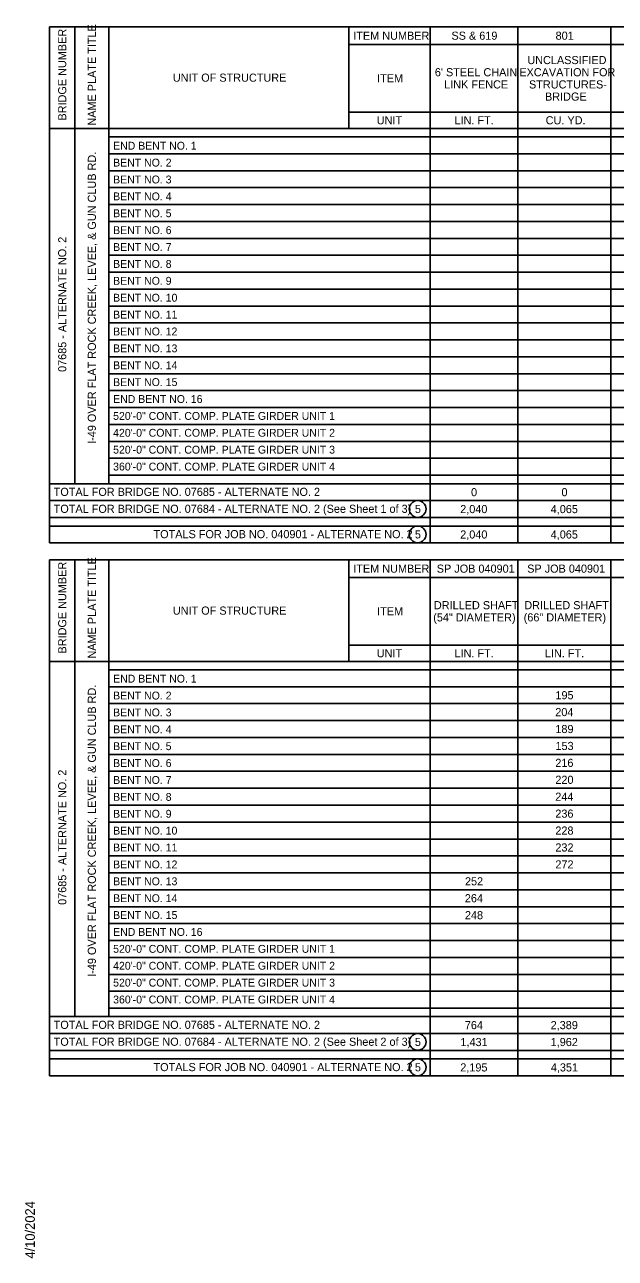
# Model space of a CAD drawing. Extents: x 0.06 to 1.36, y 0.04 to 0.85.
# Drawn here: x 0.06 to 0.423, y 0.079 to 0.838 of the extents above; entities that cross this region are included whole.
import ezdxf

# ---------------------------------------------------------------- set-up
doc = ezdxf.new("R2010")
doc.units = 0
for name, color, linetype in [('R_Shade By Others', 7, 'Continuous'), ('R_Survey Control', 7, 'Continuous'), ('R_Wall', 7, 'Continuous')]:
    doc.layers.add(name, color=color, linetype=linetype)

msp = doc.modelspace()

# ---------------------------------------------------------------- linework, layer by layer
at = {"layer": 'R_Survey Control'}
for p, q in [((0.07508, 0.51924), (0.07508, 0.83695)), ((0.07508, 0.83695), (1.33392, 0.83695)), ((0.09071, 0.5557), (0.09071, 0.83695)), ((0.11154, 0.5557), (0.11154, 0.83695)), ((0.11154, 0.77445), (0.11154, 0.83695)), ((0.2593, 0.77445), (0.2593, 0.83695)), ((0.30915, 0.83695), (0.30915, 0.51924)), ((0.36311, 0.83695), (0.36311, 0.51924)), ((0.4204, 0.83695), (0.4204, 0.51924)), ((0.2593, 0.78445), (1.33392, 0.78445)), ((0.07508, 0.77445), (1.33392, 0.77445)), ((0.11154, 0.76924), (1.33392, 0.76924)), ((0.11154, 0.75883), (1.33392, 0.75883)), ((0.11154, 0.74841), (1.33392, 0.74841)), ((0.11154, 0.73799), (1.33392, 0.73799)), ((0.11154, 0.72758), (1.33392, 0.72758)), ((0.11154, 0.71716), (1.33392, 0.71716)), ((0.11154, 0.70674), (1.33392, 0.70674)), ((0.11154, 0.69633), (1.33392, 0.69633)), ((0.11154, 0.68591), (1.33392, 0.68591)), ((0.11154, 0.67549), (1.33392, 0.67549)), ((0.11154, 0.66508), (1.33392, 0.66508)), ((0.11154, 0.65466), (1.33392, 0.65466)), ((0.11154, 0.64424), (1.33392, 0.64424)), ((0.11154, 0.63383), (1.33392, 0.63383)), ((0.11154, 0.62341), (1.33392, 0.62341)), ((0.11154, 0.61299), (1.33392, 0.61299)), ((0.11154, 0.60258), (1.33392, 0.60258)), ((0.11154, 0.59216), (1.33392, 0.59216)), ((0.11154, 0.58174), (1.33392, 0.58174)), ((0.11154, 0.57133), (1.33392, 0.57133)), ((0.07508, 0.5557), (1.33392, 0.5557)), ((0.11154, 0.56091), (1.33392, 0.56091)), ((0.07508, 0.54529), (1.33392, 0.54529)), ((0.07508, 0.53487), (1.33392, 0.53487)), ((0.07508, 0.52966), (1.33392, 0.52966)), ((0.07508, 0.51924), (1.33392, 0.51924)), ((0.07508, 0.19112), (0.07508, 0.50883)), ((0.07508, 0.50883), (1.30054, 0.50883)), ((0.09071, 0.22758), (0.09071, 0.50883)), ((0.11154, 0.22758), (0.11154, 0.50883)), ((0.11154, 0.44633), (0.11154, 0.50883)), ((0.2593, 0.44633), (0.2593, 0.50883)), ((0.30915, 0.50883), (0.30915, 0.19112)), ((0.36311, 0.50883), (0.36311, 0.19112)), ((0.4204, 0.50883), (0.4204, 0.19112)), ((0.2593, 0.45633), (1.30054, 0.45633)), ((0.07508, 0.44633), (1.30054, 0.44633)), ((0.11154, 0.44112), (1.30054, 0.44112)), ((0.11154, 0.4307), (1.30054, 0.4307)), ((0.11154, 0.42029), (1.30054, 0.42029)), ((0.11154, 0.40987), (1.30054, 0.40987)), ((0.11154, 0.39945), (1.30054, 0.39945)), ((0.11154, 0.38904), (1.30054, 0.38904)), ((0.11154, 0.37862), (1.30054, 0.37862)), ((0.11154, 0.3682), (1.30054, 0.3682)), ((0.11154, 0.35779), (1.30054, 0.35779)), ((0.11154, 0.34737), (1.30054, 0.34737)), ((0.11154, 0.33695), (1.30054, 0.33695)), ((0.11154, 0.32654), (1.30054, 0.32654)), ((0.11154, 0.31612), (1.30054, 0.31612)), ((0.11154, 0.3057), (1.30054, 0.3057)), ((0.11154, 0.29529), (1.30054, 0.29529)), ((0.11154, 0.28487), (1.30054, 0.28487)), ((0.11154, 0.27445), (1.30054, 0.27445)), ((0.11154, 0.26404), (1.30054, 0.26404)), ((0.11154, 0.25362), (1.30054, 0.25362)), ((0.11154, 0.2432), (1.30054, 0.2432)), ((0.11154, 0.23279), (1.30054, 0.23279)), ((0.07508, 0.22758), (1.30054, 0.22758)), ((0.07508, 0.21716), (1.30054, 0.21716)), ((0.07508, 0.20674), (1.30054, 0.20674)), ((0.07508, 0.20154), (1.30054, 0.20154)), ((0.07508, 0.19112), (1.30054, 0.19112))]:
    msp.add_line(p, q, dxfattribs=at)
for points in [[(0.2593, 0.82612), (0.30425, 0.82612), (0.41883, 0.82612), (0.46733, 0.82612), (0.509, 0.82612), (0.55587, 0.82612), (0.59233, 0.82612), (0.6366, 0.82612), (0.68087, 0.82612), (0.74858, 0.82612), (0.79433, 0.82612), (0.84642, 0.82612), (0.94537, 0.82612), (1.00267, 0.82612), (1.06517, 0.82612), (1.19277, 0.82612), (1.26048, 0.82612), (1.31256, 0.82612), (1.33392, 0.82612)], [(0.2593, 0.49799), (0.30425, 0.49799), (0.36154, 0.49799), (0.40321, 0.49799), (0.44487, 0.49799), (0.49175, 0.49799), (0.52821, 0.49799), (0.58029, 0.49799), (0.64019, 0.49799), (0.7079, 0.49799), (0.75998, 0.49799), (0.81206, 0.49799), (0.85894, 0.49799), (0.86623, 0.49799), (0.92873, 0.49799), (0.99644, 0.49799), (1.06415, 0.49799), (1.11623, 0.49799), (1.16831, 0.49799), (1.30054, 0.49799)]]:
    msp.add_lwpolyline(points, dxfattribs=at)
at = {"layer": 'R_Wall'}
for p, q in [((0.07508, 0.77445), (0.09071, 0.77445)), ((0.09071, 0.77445), (0.11154, 0.77445)), ((0.07508, 0.44633), (0.09071, 0.44633)), ((0.09071, 0.44633), (0.11154, 0.44633))]:
    msp.add_line(p, q, dxfattribs=at)
for centre in [(0.30155, 0.54014), (0.30155, 0.52451), (0.30155, 0.21201), (0.30155, 0.19639)]:
    msp.add_circle(centre, 0.00515, dxfattribs=at)

# ---------------------------------------------------------------- texts
at = {"layer": 'R_Shade By Others'}
msp.add_text('4/10/2024', height=0.00595, rotation=89.99995, dxfattribs=at).set_placement((0.06607, 0.0786))
at = {"layer": 'R_Survey Control'}
for s, p in [('NAME PLATE TITLE', (0.10362, 0.77619)), ('BRIDGE NUMBER', (0.0854, 0.77929)), ('I-49 OVER FLAT ROCK CREEK, LEVEE, & GUN CLUB RD.', (0.10362, 0.58025)), ('07685 - ALTERNATE NO. 2', (0.0854, 0.62452)), ('NAME PLATE TITLE', (0.10362, 0.44806)), ('BRIDGE NUMBER', (0.0854, 0.45116)), ('I-49 OVER FLAT ROCK CREEK, LEVEE, & GUN CLUB RD.', (0.10362, 0.25212)), ('07685 - ALTERNATE NO. 2', (0.0854, 0.2964))]:
    msp.add_text(s, height=0.005, rotation=90, dxfattribs=at).set_placement(p)
for s, height, p in [('ITEM NUMBER', 0.005, (0.26194, 0.82904)), ('SS & 619', 0.005, (0.32235, 0.82904)), ('801', 0.005, (0.3864, 0.82904)), ('UNCLASSIFIED', 0.005, (0.36903, 0.81404)), ('UNIT OF STRUCTURE', 0.005, (0.15095, 0.8032)), ('ITEM', 0.005, (0.27661, 0.80279)), ("6' STEEL CHAIN", 0.005, (0.31212, 0.80654)), ('EXCAVATION FOR ', 0.005, (0.36408, 0.80654)), ('LINK FENCE', 0.005, (0.31785, 0.79904)), ('STRUCTURES-', 0.005, (0.37004, 0.79904)), ('BRIDGE', 0.005, (0.37987, 0.79154)), ('UNIT', 0.005, (0.27638, 0.77695)), ('LIN. FT.', 0.005, (0.32421, 0.77695)), ('CU. YD.', 0.005, (0.38029, 0.77695)), ('END BENT NO. 1', 0.0048358, (0.11421, 0.76137)), ('BENT NO. 2', 0.004836, (0.11421, 0.75098)), ('BENT NO. 3', 0.004836, (0.11421, 0.74058)), ('BENT NO. 4', 0.004836, (0.11421, 0.73018)), ('BENT NO. 5', 0.004836, (0.11421, 0.71979)), ('BENT NO. 6', 0.004836, (0.11421, 0.70939)), ('BENT NO. 7', 0.004836, (0.11421, 0.69899)), ('BENT NO. 8', 0.004836, (0.11421, 0.6886)), ('BENT NO. 9', 0.004836, (0.11421, 0.6782)), ('BENT NO. 10', 0.0048358, (0.11421, 0.6678)), ('BENT NO. 11', 0.0048358, (0.11421, 0.65741)), ('BENT NO. 12', 0.0048358, (0.11421, 0.64701)), ('BENT NO. 13', 0.0048358, (0.11421, 0.63661)), ('BENT NO. 14', 0.0048358, (0.11421, 0.62621)), ('BENT NO. 15', 0.0048358, (0.11421, 0.61582)), ('END BENT NO. 16', 0.0048358, (0.11421, 0.60542)), ('520\'-0" CONT. COMP. PLATE GIRDER UNIT 1', 0.0048358, (0.11421, 0.59502)), ('420\'-0" CONT. COMP. PLATE GIRDER UNIT 2', 0.0048358, (0.11421, 0.58463)), ('520\'-0" CONT. COMP. PLATE GIRDER UNIT 3', 0.0048358, (0.11421, 0.57423)), ('360\'-0" CONT. COMP. PLATE GIRDER UNIT 4', 0.0048358, (0.11421, 0.56383)), ('TOTAL FOR BRIDGE NO. 07685 - ALTERNATE NO. 2', 0.005, (0.07763, 0.54818)), ('0', 0.005, (0.33439, 0.54799)), ('0', 0.005, (0.39001, 0.54799)), ('TOTAL FOR BRIDGE NO. 07684 - ALTERNATE NO. 2 (See Sheet 1 of 3)', 0.005, (0.07763, 0.53776)), ('2,040', 0.005, (0.32772, 0.53758)), ('4,065', 0.005, (0.38339, 0.53758)), ('TOTALS FOR JOB NO. 040901 - ALTERNATE NO. 2', 0.005, (0.13905, 0.52216)), ('2,040', 0.005, (0.32772, 0.52195)), ('4,065', 0.005, (0.38339, 0.52195)), ('ITEM NUMBER', 0.005, (0.26194, 0.50091)), ('SP JOB 040901', 0.005, (0.3133, 0.50091)), ('SP JOB 040901', 0.005, (0.36892, 0.50091)), ('UNIT OF STRUCTURE', 0.005, (0.15095, 0.47508)), ('ITEM', 0.005, (0.27661, 0.47466)), ('DRILLED SHAFT', 0.005, (0.31153, 0.47841)), ('DRILLED SHAFT', 0.005, (0.36715, 0.47841)), ('(54" DIAMETER)', 0.005, (0.31114, 0.47091)), ('(66" DIAMETER)', 0.005, (0.36677, 0.47091)), ('UNIT', 0.005, (0.27638, 0.44883)), ('LIN. FT.', 0.005, (0.32421, 0.44883)), ('LIN. FT.', 0.005, (0.37983, 0.44883)), ('END BENT NO. 1', 0.0048358, (0.11421, 0.43325)), ('BENT NO. 2', 0.004836, (0.11421, 0.42285)), ('195', 0.005, (0.3863, 0.42299)), ('BENT NO. 3', 0.004836, (0.11421, 0.41246)), ('204', 0.005, (0.38621, 0.41258)), ('BENT NO. 4', 0.004836, (0.11421, 0.40206)), ('189', 0.005, (0.38627, 0.40216)), ('BENT NO. 5', 0.004836, (0.11421, 0.39166)), ('153', 0.005, (0.38632, 0.39174)), ('BENT NO. 6', 0.004836, (0.11421, 0.38127)), ('216', 0.005, (0.38624, 0.38133)), ('BENT NO. 7', 0.004836, (0.11421, 0.37087)), ('220', 0.005, (0.38626, 0.37091)), ('BENT NO. 8', 0.004836, (0.11421, 0.36047)), ('244', 0.005, (0.38621, 0.36049)), ('BENT NO. 9', 0.004836, (0.11421, 0.35007)), ('236', 0.005, (0.38624, 0.35008)), ('BENT NO. 10', 0.0048358, (0.11421, 0.33968)), ('228', 0.005, (0.38625, 0.33966)), ('232', 0.005, (0.38628, 0.32924)), ('BENT NO. 11', 0.0048358, (0.11421, 0.32928)), ('BENT NO. 12', 0.0048358, (0.11421, 0.31888)), ('272', 0.005, (0.38628, 0.31883)), ('BENT NO. 13', 0.0048358, (0.11421, 0.30849)), ('252', 0.005, (0.33065, 0.30841)), ('BENT NO. 14', 0.0048358, (0.11421, 0.29809)), ('264', 0.005, (0.33058, 0.29799)), ('BENT NO. 15', 0.0048358, (0.11421, 0.28769)), ('248', 0.005, (0.33062, 0.28758)), ('END BENT NO. 16', 0.0048358, (0.11421, 0.2773)), ('520\'-0" CONT. COMP. PLATE GIRDER UNIT 1', 0.0048358, (0.11421, 0.2669)), ('420\'-0" CONT. COMP. PLATE GIRDER UNIT 2', 0.0048358, (0.11421, 0.2565)), ('520\'-0" CONT. COMP. PLATE GIRDER UNIT 3', 0.0048358, (0.11421, 0.2461)), ('360\'-0" CONT. COMP. PLATE GIRDER UNIT 4', 0.0048358, (0.11421, 0.23571)), ('TOTAL FOR BRIDGE NO. 07685 - ALTERNATE NO. 2', 0.005, (0.07763, 0.22006)), ('764', 0.005, (0.33058, 0.21987)), ('2,389', 0.005, (0.38335, 0.21987)), ('TOTAL FOR BRIDGE NO. 07684 - ALTERNATE NO. 2 (See Sheet 2 of 3)', 0.005, (0.07763, 0.20964)), ('1,431', 0.005, (0.32786, 0.20945)), ('1,962', 0.005, (0.38336, 0.20945)), ('TOTALS FOR JOB NO. 040901 - ALTERNATE NO. 2', 0.005, (0.13905, 0.19403)), ('2,195', 0.005, (0.32776, 0.19383)), ('4,351', 0.005, (0.38348, 0.19383))]:
    msp.add_text(s, height=height, dxfattribs=at).set_placement(p)
at = {"layer": 'R_Wall'}
for p in [(0.29985, 0.53764), (0.29985, 0.52201), (0.29985, 0.20951), (0.29985, 0.19389)]:
    msp.add_text('5', height=0.005, dxfattribs=at).set_placement(p)

doc.saveas('drawing.dxf')
